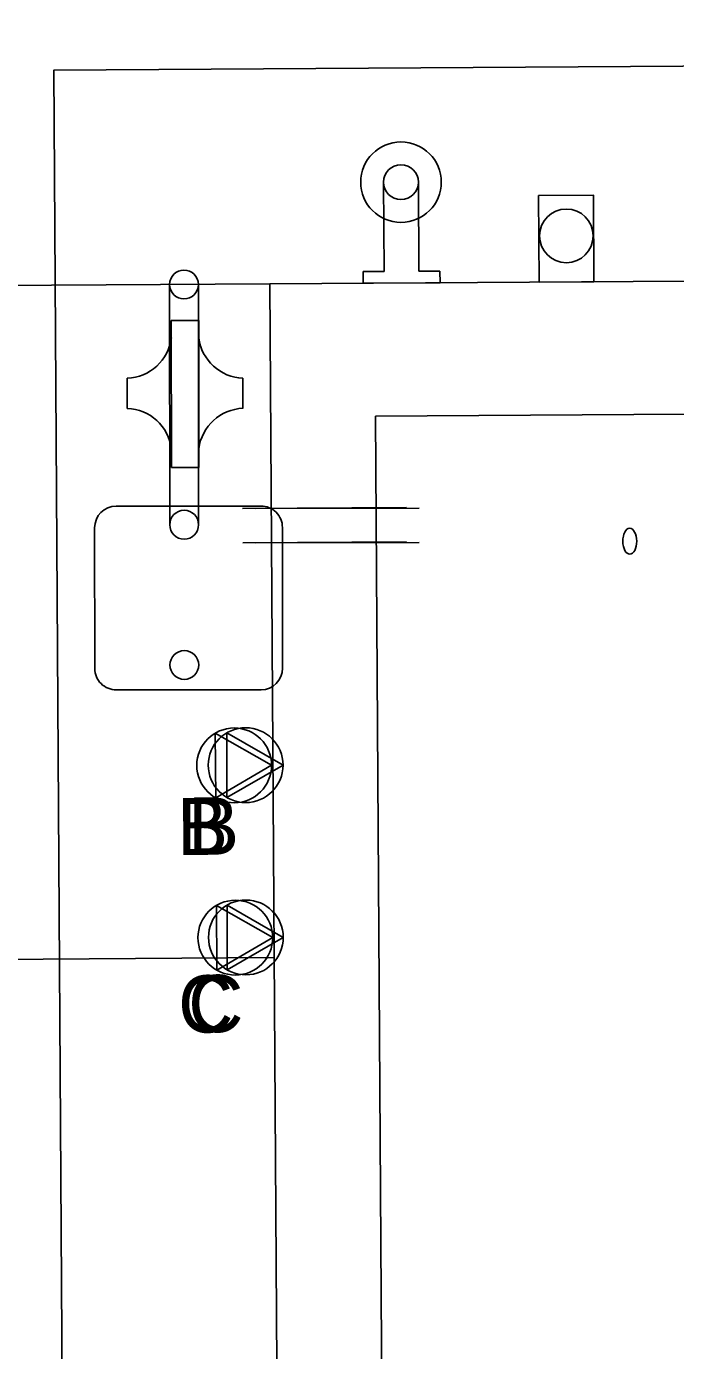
# Model space of a CAD drawing. Extents: x -2.6 to 16.3, y -2.7 to 7.5.
# Drawn here: x -0.108 to 1.404, y 4.018 to 7.102 of the extents above; entities that cross this region are included whole.
import ezdxf

# ---------------------------------------------------------------- set-up
doc = ezdxf.new("R2010")
doc.units = 0
for name, color, linetype in [('HS_Concrete_Object', 7, 'Continuous'), ('HS_Dimensions_and_Text', 7, 'Continuous'), ('HS_Electrical_Conduit', 7, 'Continuous'), ('HS_Electrical_Devices', 7, 'Continuous'), ('SH_General_Details', 7, 'Continuous')]:
    doc.layers.add(name, color=color, linetype=linetype)

msp = doc.modelspace()

# ---------------------------------------------------------------- linework, layer by layer
at = {"layer": 'HS_Concrete_Object'}
for p, q in [((0.7238, 6.739), (0.7252, 6.5311)), ((0.8051, 6.7395), (0.8064, 6.5316)), ((0.7252, 6.5311), (0.6763, 6.5308)), ((0.6763, 6.5308), (0.6763, 6.5308)), ((0.6763, 6.5308), (0.6765, 6.5039)), ((0.8064, 6.5316), (0.8552, 6.5319)), ((0.8552, 6.5319), (0.8552, 6.5319)), ((0.8552, 6.5319), (0.8554, 6.505)), ((0.6765, 6.5039), (0.8554, 6.505))]:
    msp.add_line(p, q, dxfattribs=at)
for points in [[(15.9556, 7.1018), (-0.0446, 6.9998), (0, 0), (16.0002, 0.1019)], [(1.0848, 6.7084), (1.2128, 6.7092), (1.2141, 6.5073), (1.0861, 6.5065)], [(0.4629, 5.3815), (0.3328, 5.3052), (0.3318, 5.4561)], [(0.4656, 4.9802), (0.3354, 4.9039), (0.3345, 5.0548)]]:
    msp.add_lwpolyline(points, close=True, dxfattribs=at)
for points in [[(15.4629, 5.9473), (15.4588, 6.5986), (0.4591, 6.5025), (0.4974, 0.5032), (0.9916, 0.5063)], [(0.7399, 0.7823), (0.7054, 6.1941), (15.1483, 6.2872)]]:
    msp.add_lwpolyline(points, dxfattribs=at)
for centre, radius in [((0.7644, 6.7392), 0.0938), ((0.7644, 6.7392), 0.0406), ((1.1497, 6.6142), 0.0625), ((0.3758, 5.3809), 0.0871), ((0.3785, 4.9797), 0.0871)]:
    msp.add_circle(centre, radius, dxfattribs=at)
at = {"layer": 'HS_Dimensions_and_Text'}
for p, q in [((0.4591, 6.5025), (-1.0408, 6.4929)), ((0.4691, 4.9333), (-1.0308, 4.9237))]:
    msp.add_line(p, q, dxfattribs=at)
at = {"layer": 'HS_Electrical_Conduit'}
msp.add_ellipse((1.2975, 5.9029), major_axis=(0.0002, -0.0302), ratio=0.534795, dxfattribs=at)
at = {"layer": 'HS_Electrical_Devices'}
for p, q in [((0.2258, 5.9414), (0.2253, 6.5007)), ((0.2929, 5.9415), (0.2924, 6.5008)), ((0.2931, 6.4172), (0.2293, 6.4172)), ((0.2296, 6.0749), (0.2293, 6.4172)), ((0.2934, 6.0749), (0.2931, 6.4172)), ((0.1265, 6.2124), (0.1264, 6.2825)), ((0.3963, 6.2126), (0.3962, 6.2827)), ((0.2934, 6.0749), (0.2296, 6.0749)), ((0.4382, 5.9849), (0.1007, 5.9846)), ((0.4254, 5.9793), (0.807, 5.9797)), ((0.0507, 5.9345), (0.051, 5.6066)), ((0.4882, 5.9349), (0.4885, 5.607)), ((0.8071, 5.9), (0.4255, 5.8996)), ((0.4386, 5.557), (0.1011, 5.5567))]:
    msp.add_line(p, q, dxfattribs=at)
for points in [[(0.4896, 5.3816), (0.359, 5.306), (0.3589, 5.4569)], [(0.4901, 4.9803), (0.3595, 4.9047), (0.3594, 5.0556)]]:
    msp.add_lwpolyline(points, close=True, dxfattribs=at)
for centre, radius in [((0.2588, 6.5008), 0.0336), ((0.2593, 5.9414), 0.0336), ((0.2596, 5.6148), 0.0336), ((0.4025, 5.3815), 0.0871), ((0.403, 4.9802), 0.0871)]:
    msp.add_circle(centre, radius, dxfattribs=at)
for centre, radius, start, end in [((0.1222, 6.3904), 0.108, 272.2589, 352.8141), ((0.4003, 6.3906), 0.108, 187.2906, 267.8458), ((0.1224, 6.1045), 0.108, 7.2906, 87.8458), ((0.4006, 6.1047), 0.108, 92.2589, 172.8141), ((0.1007, 5.9346), 0.05, 90.0523, 180.0523), ((0.4382, 5.9349), 0.05, 0.0523, 90.0523), ((0.101, 5.6067), 0.05, 180.0523, 270.0523), ((0.4385, 5.607), 0.05, 270.0523, 0.0523)]:
    msp.add_arc(centre, radius, start, end, dxfattribs=at)
at = {"layer": 'SH_General_Details'}
for p, q in [((0.3955, 5.9789), (0.7771, 5.9813)), ((0.7776, 5.9016), (0.396, 5.8992))]:
    msp.add_line(p, q, dxfattribs=at)

# ---------------------------------------------------------------- texts
at = {"layer": 'HS_Concrete_Object'}
for s, p in [('B', (0.2428, 5.1718)), ('C', (0.2455, 4.7583))]:
    msp.add_text(s, height=0.1333, rotation=0.365, dxfattribs=at).set_placement(p)
at = {"layer": 'HS_Electrical_Devices'}
for s, p in [('B', (0.2684, 5.173)), ('C', (0.2687, 4.7595))]:
    msp.add_text(s, height=0.1333, rotation=0.0523, dxfattribs=at).set_placement(p)

doc.saveas('drawing.dxf')
